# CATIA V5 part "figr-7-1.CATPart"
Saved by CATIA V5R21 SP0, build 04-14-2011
Part number: Part1
Bounding box of the stored display mesh (mm): x -50 to 50, y -75 to 75, z 0 to 10
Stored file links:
  D:\CATIA V5R21 E-RESOURCES\CATIA-V5R21\catia-v5r21-prt\c07-catia-v5r20-prt\c07-catia-v5r21-figr-7-1.CATPart
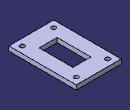
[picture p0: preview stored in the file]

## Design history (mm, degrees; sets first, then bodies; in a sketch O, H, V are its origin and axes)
Body1 (main body)
  Sketch1 on xy-plane, origin (0, 0, 0), H (1, 0, 0), V (0, 1, 0)
    line L1 (-50, 75) -> (50, 75)
    line L2 (50, 75) -> (50, -75)
    line L3 (50, -75) -> (-50, -75)
    line L4 (-50, -75) -> (-50, 75)
    axis line L5 (50, -75) -> (-50, 75)
    length L3 = 100
    length L2 = 150
    horizontal: L1 H, L3 H
    vertical: L2 V, L4 V
    midpoint: O L5
  Pad1: profile Sketch1, direction (0, 0, 1), length 10
  Sketch2 on face of Pad1, origin (0, 0, 10), H (1, 0, 0), V (0, 1, 0)
    line L1 (-20, 37.5) -> (20, 37.5)
    line L2 (20, 37.5) -> (20, -37.5)
    line L3 (20, -37.5) -> (-20, -37.5)
    line L4 (-20, -37.5) -> (-20, 37.5)
    axis line L5 (20, -37.5) -> (-20, 37.5)
    length L3 = 40
    length L2 = 75
    horizontal: L1 H, L3 H
    vertical: L2 V, L4 V
    midpoint: O L5
  Pocket1: profile Sketch2, direction (0, 0, -1), through (limit type 3)
  Sketch3 on face of Pad1, origin (-33.8832, 14.5619, 10), H (1, 0, 0), V (0, 1, 0)
    point P1 (68.8832, -74.5619)
    reference projected line E1 (-16.1168, -89.5619) -> (83.8832, -89.5619) from edge [face of Pad1 | face of Pad1]
    reference projected line E2 (83.8832, -89.5619) -> (83.8832, 60.4381) from edge [face of Pad1 | face of Pad1]
    distance P1 E1 = 15
    distance P1 E2 = 15
  Hole1: placed by Sketch3, at (35, -60, 10) direction (0, 0, -1), diameter 10, through (limit type 3)
  RectPattern1: of Hole1, direction 1 instances 2, spacing 70, along edge [face of Pad1 | face of Pad1] reversed, direction 2 instances 2, spacing 120, along edge [face of Pad1 | face of Pad1]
